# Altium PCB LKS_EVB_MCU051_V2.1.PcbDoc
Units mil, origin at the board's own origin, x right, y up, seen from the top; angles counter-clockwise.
Board outline 2625 x 1560 mil, 2 copper layers (Top Layer, Bottom Layer); 44 components, 64 nets, 193 pads, 54 vias.
Unrouted connection lines stored in the file: 24.
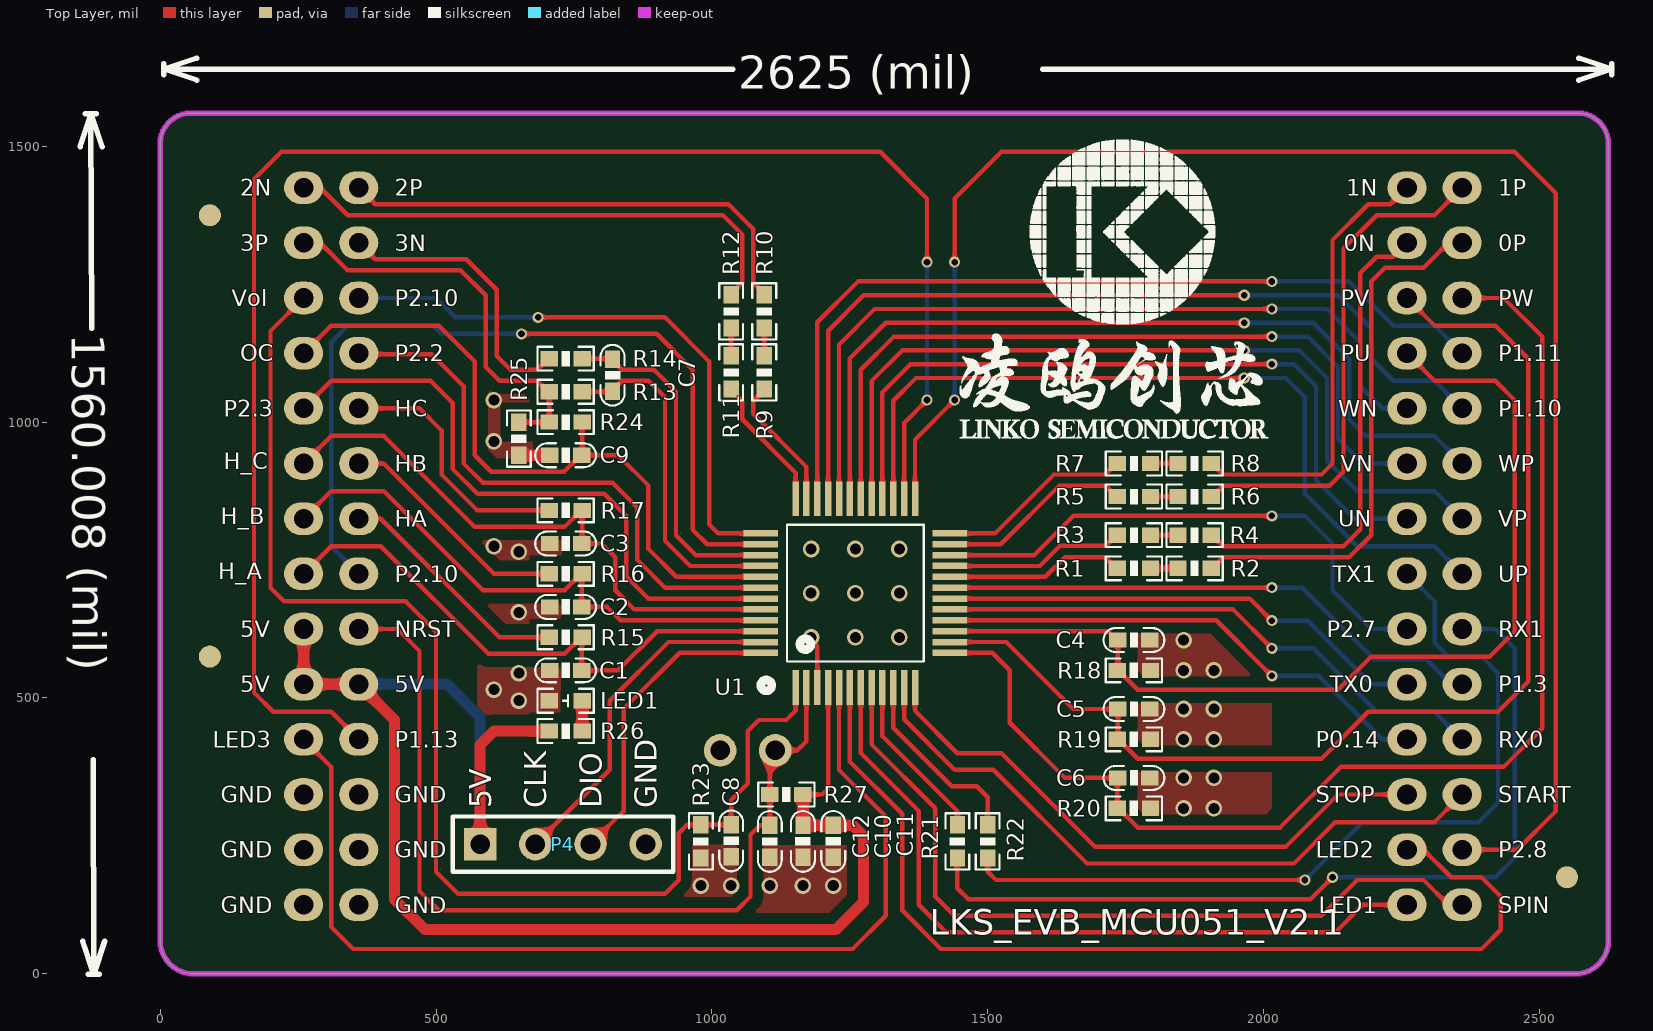
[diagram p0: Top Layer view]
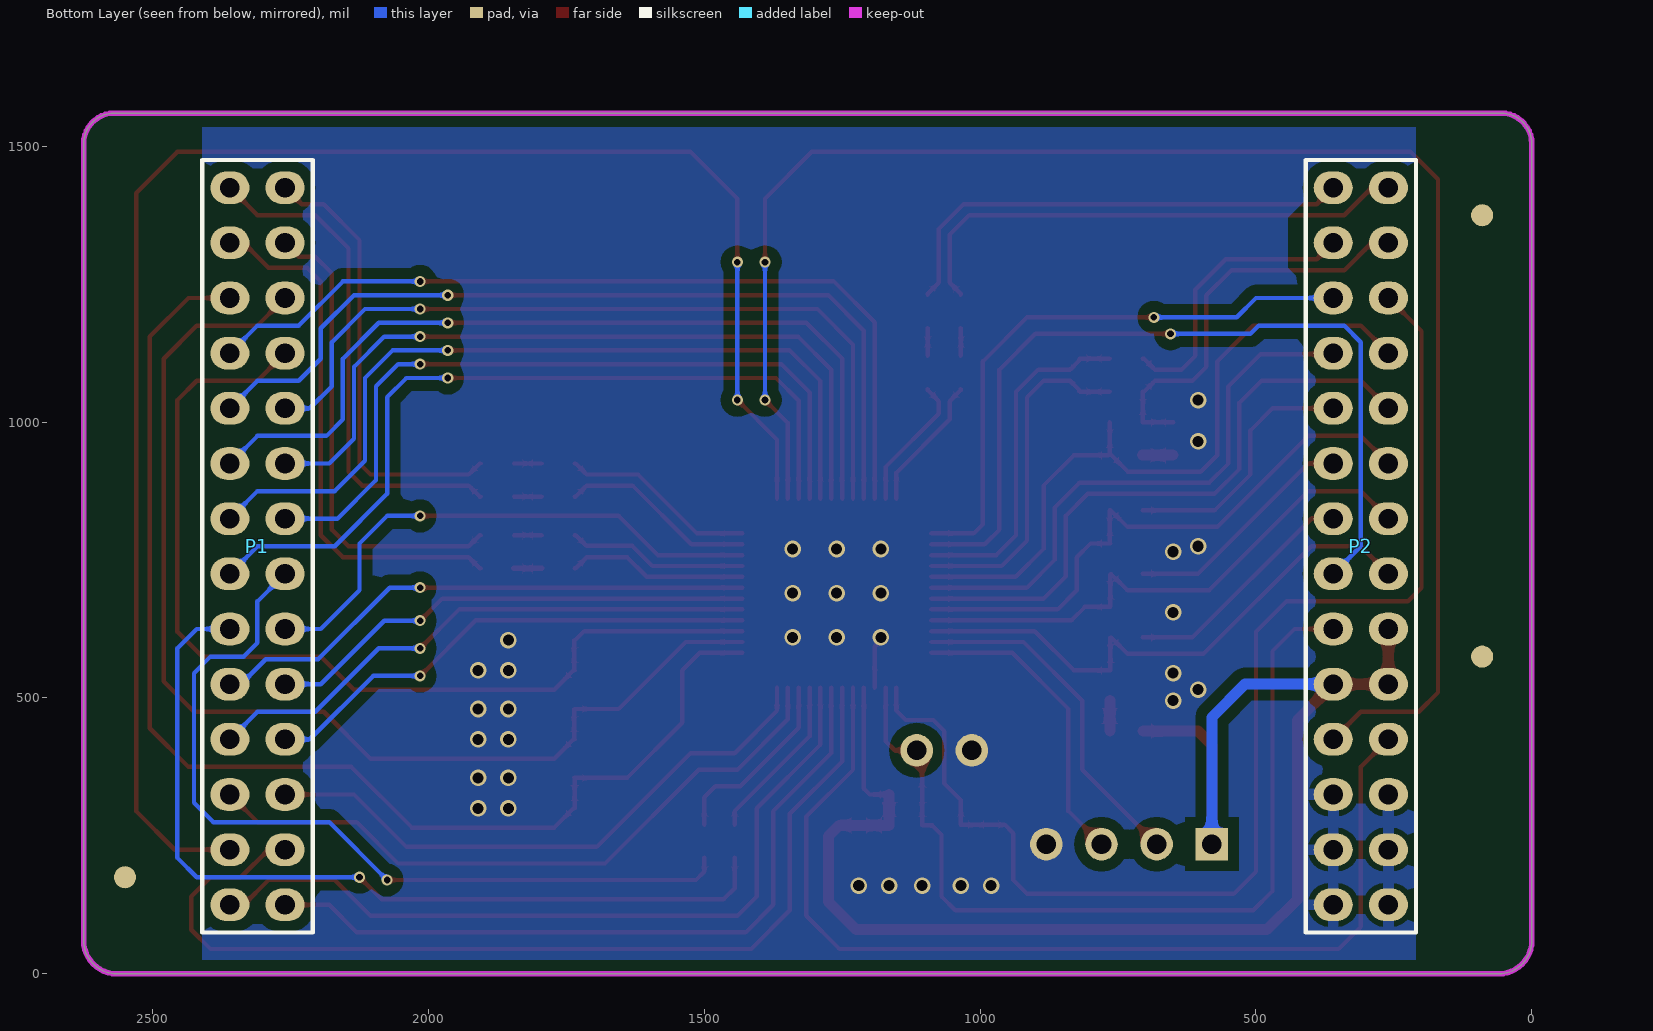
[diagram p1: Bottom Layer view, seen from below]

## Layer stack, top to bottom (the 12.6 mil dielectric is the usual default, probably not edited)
Top Solder: solder mask 0.4, Solder Resist, Dk 3.5
Top Layer: signal copper 1.4
Dielectric1: dielectric 12.6, FR-4, Dk 4.8
Bottom Layer: signal copper 1.4
Bottom Solder: solder mask 0.4, Solder Resist, Dk 3.5

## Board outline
0,60 ccw(c60,60) 60,0 2565,0 ccw(c2565,60) 2625,60 2625,1505 ccw(c2570,1505) 2570,1560 55,1560 ccw(c55,1505) 0,1505

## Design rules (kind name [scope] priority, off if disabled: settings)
Clearance Clearance_2 [InPolygon] p1: gap=20 ignorepadtopadclearanceinfootprint=FALSE except(0: Arc-Hole Track-Hole SMDPad-Hole THPad-Hole Via-Hole Fill-Hole Poly-Hole Region-Hole Text-Hole)
Clearance Clearance_1 [All] p2: gap=7.87 ignorepadtopadclearanceinfootprint=FALSE except(0: Arc-Hole Track-Hole SMDPad-Hole THPad-Hole Via-Hole Fill-Hole Poly-Hole Region-Hole Text-Hole)
ComponentClearance [All] p1: gap=0 collisioncheckmode=3 verticalgap=0 showdistances=FALSE
FabricationTestpoint [(IsPad And (OnTopLayer Or OnBottomLayer))] p1: side=3 testpointundercomponent=TRUE minsize=40 maxsize=100 preferedsize=60 minholesize=0 maxholesize=40 preferedholesize=32 testpointgrid=1 allowsidetop=TRUE allowsidebottom=TRUE usegrid=TRUE gridtolerance=0.01
PolygonConnect PolygonConnect_1 [HasFootprint('HDR 2X14 顶层') vs InNet('GND')] p1: connectstyle=Relief reliefconductorwidth=20 reliefentries=4 polygonreliefangle="90 Angle" airgapwidth=10
PolygonConnect [All] p2: connectstyle=Direct reliefconductorwidth=20 reliefentries=4 polygonreliefangle="90 Angle" airgapwidth=10
RoutingVias [All] p1: holewidth=11.81 width=23.62 viastyle="Through Hole" minholewidth=0 minwidth=11.81 maxholewidth=23.62 maxwidth=78.74
SilkToSolderMaskClearance SilkscreenOverComponentPads [IsPad] p1: minsilkscreentomaskgap=10 clearancetoexposedcopper=TRUE
SolderMaskExpansion [All] p1: expansion=4 istentingtop=FALSE
Width [All] p1: maxlimit=100 minlimit=1 preferedwidth=10
27 further rules are at their usual default settings.

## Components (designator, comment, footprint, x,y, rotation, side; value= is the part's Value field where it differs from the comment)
C1 "10nF/16V" 0603C 735,550 r180 top
C2 "10nF/16V" 0603C 735,665 r180 top
C3 "10nF/16V" 0603C 735,780 r180 top
C4 "1nF/16V" 0603C 1765,605 r0 top
C5 "1nF/16V" 0603C 1765,480 r0 top
C6 "1nF/16V" 0603C 1765,355 r0 top
C7 "1nF/10V" 0603C 820,1085 r90 top
C8 "100nF/50V" 0603C 1035,240.95 r90 top
C9 "1nF/50V" 0603C 735,940 r0 top
C10 "10uF/10V" 0603C 1165,240 r90 top
C11 "100nF/50V" 0603C 1220,240 r90 top
C12 "100nF/50V" 0603C 1105,240 r270 top
LED1 "LED" "LED 0603R" 735,495 r180 top
P1 "Header 14X2A" "HDR 2X14 顶层" 2310,775 r180 bottom locked
P2 "Header 14X2A" "HDR 2X14 顶层" 310,775 r180 bottom locked
P4 "Header 4" HDR1X4 580,235 r0 top
R1 "20K1%" 0603R 1765,735 r180 top value=K
R2 "20K1%" 0603R 1875,735 r180 top value=K
R3 "20K1%" 0603R 1765,795 r180 top value=K
R4 "20K1%" 0603R 1875,795 r180 top value=K
R5 "20K1%" 0603R 1765,865 r180 top value=K
R6 "20K1%" 0603R 1875,865 r180 top value=K
R7 "20K1%" 0603R 1765,925 r180 top value=K
R8 "20K1%" 0603R 1875,925 r180 top value=K
R9 "20K1%" 0603R 1095,1090 r270 top value=K
R10 "20K1%" 0603R 1095,1200.65 r270 top value=K
R11 "20K1%" 0603R 1035,1090 r270 top value=K
R12 "20K1%" 0603R 1035,1200.65 r270 top value=K
R13 "1K1%" 0603R 735,1055 r0 top value=K
R14 "1K1%" 0603R 735,1115 r0 top value=K
R15 "2K" 0603R 735,610 r0 top value=K
R16 "2K" 0603R 735,725 r0 top value=K
R17 "2K" 0603R 735,840 r0 top value=K
R18 "1K" 0603R 1765,550 r0 top value=K
R19 "1K" 0603R 1765,425 r0 top value=K
R20 "1K" 0603R 1765,300 r0 top value=K
R21 "10R" 0603R 1445,240 r90 top value=K
R22 "10R" 0603R 1500,240 r90 top value=K
R23 "1K1%" 0603R 980,240 r90 top value=K
R24 "1K1%" 0603R 735,1000 r180 top value=K
R25 "10R" 0603R 650,970 r270 top value=K
R26 "330R" 0603R 735,440 r0 top value=330
R27 "20K" 0603R 1135,325 r0 top value=K
U1 "LKS32MC051C6T8" TQFP48 1260,690 r0 top locked

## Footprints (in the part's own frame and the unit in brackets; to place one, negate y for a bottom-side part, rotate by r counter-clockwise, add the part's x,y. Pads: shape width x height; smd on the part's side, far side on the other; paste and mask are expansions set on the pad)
0603C [mm] "电容"
  rect 0.8x0.7 smd: 1(-0.737,0) 2(0.738,0)
  silkscreen extent -1.4,-0.55 1.4,0.55, body extent -0.8,-0.41 0.8,0.41, height 0.81
0603R [mm] "电阻"
  rect 0.8x0.7 smd: 1(-0.762,0) 2(0.762,0)
  silkscreen extent -1.3,-0.55 1.3,0.55, body extent -0.8,-0.4 0.8,0.4, height 0.45
HDR1X4 [mm] "Connector; Header; 4 Position"
  rect 1.5x1.5 hole 0.9: 1(0,0)
  round 1.5 hole 0.9: 2(2.54,0) 3(5.08,0) 4(7.62,0)
  silkscreen extent -1.27,-1.27 8.89,1.27
"HDR 2X14 顶层" [mm] "双排针 2.54mm 顶层"
  oval 1.8x1.5 hole 0.9: 1(1.27,16.51) 2(1.27,13.97) 3(1.27,11.43) 4(1.27,8.89) 5(1.27,6.35) 6(1.27,3.81) 7(1.27,1.27) 8(1.27,-1.27) 9(1.27,-3.81) 10(1.27,-6.35) 11(1.27,-8.89) 12(1.27,-11.43) 13(1.27,-13.97) 14(1.27,-16.51) 15(-1.27,16.51) 16(-1.27,13.97) 17(-1.27,11.43) 18(-1.27,8.89) 19(-1.27,6.35) 20(-1.27,3.81) 21(-1.27,1.27) 22(-1.27,-1.27) 23(-1.27,-3.81) 24(-1.27,-6.35) 25(-1.27,-8.89) 26(-1.27,-11.43) 27(-1.27,-13.97) 28(-1.27,-16.51)
  silkscreen extent -2.54,-17.78 2.54,17.78, body extent -2.54,-17.78 2.54,17.78, height 8.5
"LED 0603R" [mm] "LED"
  rect 0.8x0.7 smd: 1(-0.762,0) 2(0.762,0)
  silkscreen extent -1.3,-0.55 1.3,0.55, body extent -0.8,-0.4 0.8,0.4, height 0.47
TQFP48 [mm] "LINKO-081/083/088/051"
  rect 0.3x1.6 smd: 1(-2.75,-4.35) 2(-2.25,-4.35) 3(-1.75,-4.35) 4(-1.25,-4.35) 5(-0.75,-4.35) 6(-0.25,-4.35) 7(0.25,-4.35) 8(0.75,-4.35) 9(1.25,-4.35) 10(1.75,-4.35) 11(2.25,-4.35) 12(2.75,-4.35) 25(2.75,4.35) 26(2.25,4.35) 27(1.75,4.35) 28(1.25,4.35) 29(0.75,4.35) 30(0.25,4.35) 31(-0.25,4.35) 32(-0.75,4.35) 33(-1.25,4.35) 34(-1.75,4.35) 35(-2.25,4.35) 36(-2.75,4.35)
  rect 1.6x0.3 smd: 13(4.35,-2.75) 14(4.35,-2.25) 15(4.35,-1.75) 16(4.35,-1.25) 17(4.35,-0.75) 18(4.35,-0.25) 19(4.35,0.25) 20(4.35,0.75) 21(4.35,1.25) 22(4.35,1.75) 23(4.35,2.25) 24(4.35,2.75) 37(-4.35,2.75) 38(-4.35,2.25) 39(-4.35,1.75) 40(-4.35,1.25) 41(-4.35,0.75) 42(-4.35,0.25) 43(-4.35,-0.25) 44(-4.35,-0.75) 45(-4.35,-1.25) 46(-4.35,-1.75) 47(-4.35,-2.25) 48(-4.35,-2.75)
  silkscreen extent -4.35,-4.5 3.15,3.15, body extent -4.5,-4.5 4.5,4.5, height 1.05

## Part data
C1 C2 C3 C4 C5 C6: library part CAP, "Capacitor"
C7 C8 C9 C10 C11 C12: library part C, "Capacitor"
LED1: "LED_Light"
P1 P2: "Header, 14-Pin, Dual row"
P4: "Header, 4-Pin"
R1 R2 R3 R4 R5 R6 R7 R8 R9 R10 R11 R12 R13 R14 R15 R16 R17 R18 R19 R20 R21 R22 R23 R24 R25 R26 R27: library part Res, "Resistor"
U1: "芯片"

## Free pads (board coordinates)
  round 59.06 hole 35.43: 1(1015,405) 1(1115,405)
  round 40 all layers, no hole: 1(2550,175) 2(90,1375) 3(90,575)

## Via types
v1: diameter 30, hole 20, Top Layer to Bottom Layer, 33 vias
v2: diameter 20, hole 12, Top Layer to Bottom Layer, 21 vias

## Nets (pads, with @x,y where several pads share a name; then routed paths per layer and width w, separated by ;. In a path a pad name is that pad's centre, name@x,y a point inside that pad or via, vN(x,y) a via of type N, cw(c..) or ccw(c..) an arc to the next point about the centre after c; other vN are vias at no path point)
+5V: C10.2 C11.2 P2.9 P2.10 P2.24 P4.1 R26.1 R27.2 U1.4 | length 2827.7
  Top Layer w8: R27.2 1200,325 1210.79,335.79 U1.4
  Top Layer w20: P2.9 P2.10 P2.24 425,460 425,135 480,80 1225,80 1275,130 1275,250 1255.94,269.06 C11.2 C10.2 R27.2 ; P4.1 580,415 605,440 R26.1
  Bottom Layer w20: P2.24 520,525 580,465 P4.1
GND: C1.2 C2.2 C3.2 C4.2 C5.2 C6.2 C8.1 C9.1 C10.1 C11.1 C12.2 LED1.2 P2.12 P2.13 P2.14 P2.16 P2.26 P2.27 P2.28 P4.4 pad.1@1015,405 R14.1 R18.2 R19.2 R20.2 R23.1 R25.2 U1.3 | length 670.7
  Top Layer w8: P2.16 390,1295 555,1295 610,1240 610,1120 635,1095 683.03,1095 703.03,1115 R14.1 ; v1(1180,610) 1180,604.05 1191.1,592.94 U1.3
  Top Layer w20: R25.2 C9.1
  other v1: 980,160 1035,160 1105,160 1165,160 1220,160 1855,300 1910,300 1855,355 1910,355 1855,425 1910,425 1855,480 1910,480 650,495 605,515 650,545 1855,550 1910,550 1855,605 1260,610 1340,610 650,655 1180,690 1260,690 1340,690 650,765 1180,770 1260,770 1340,770 605,775 605,965 605,1040
HALL_U: C1.1 P2.8 R15.2 U1.46 | length 1030.7
  Top Layer w8: P2.8 310,775 400,775 595,580 733.03,580 762.03,609 764,609 C1.1 830,550 901.1,621.1 U1.46
HALL_V: C2.1 P2.7 R16.2 U1.45 | length 1005.1
  Top Layer w8: P2.7 310,875 405,875 585,695 733.03,695 762.03,724 764,724 C2.1 810,665 834.21,640.79 U1.45
HALL_W: C3.1 P2.6 R17.2 U1.44 | length 1076.3
  Top Layer w8: P2.6 310,975 405,975 570,810 733.03,810 763.03,840 R17.2 765,781 C3.1 800,780 825,755 825,695 859.53,660.47 U1.44
HU: P2.21 R15.1 | length 434.1
  Top Layer w8: P2.21 400,825 615,610 R15.1
HV: P2.20 R16.1 | length 427.8
  Top Layer w8: P2.20 405,925 605,725 R16.1
HW: P2.19 R17.1 | length 468.5
  Top Layer w8: P2.19 470,1025 510,985 510,905 575,840 R17.1
LED1: P1.14 U1.7 | length 1363.7
  Top Layer w8: U1.7 1269.84,400.16 1375,295 1375,125 1425,75 2130,75 2180,125 P1.14
LED2: P1.13 U1.6 | length 1836.7
  Top Layer w8: U1.6 1250.16,384.84 1345,290 1345,115 1415,45 2395,45 2430,80 2430,140 2395,175 2340,175 2290,225 P1.13
LED3: P2.11 U1.5 | length 1855.9
  Top Layer w8: P2.11 310,375 310,85 350,45 1255,45 1315,105 1315,285 1230.47,369.53 U1.5
NetLED1_1: LED1.1 R26.2 | length 55
  Top Layer w20: R26.2 LED1.1
NetR1_1: R1.1 R2.2 | length 50
  Top Layer w10: R1.1 R2.2
NetR3_1: R3.1 R4.2 | length 50
  Top Layer w8: R3.1 R4.2
NetR5_1: R5.1 R6.2 | length 50
  Top Layer w8: R5.1 R6.2
NetR7_1: R7.1 R8.2 | length 50
  Top Layer w8: R7.1 R8.2
NetR9_1: R9.1 R10.2 | length 50.7
  Top Layer w8: R9.1 R10.2
NetR11_1: R11.1 R12.2 | length 50.7
  Top Layer w8: R11.1 R12.2
NetR21_2: R21.2 U1.9 | length 305
  Top Layer w8: U1.9 1309.21,430.79 1445,295 R21.2
NetR22_2: R22.2 U1.10 | length 346
  Top Layer w8: U1.10 1328.9,446.1 1435,340 1480,340 1500,320 R22.2
NRST: C12.1 P2.23 pad.1@1115,405 R27.1 U1.2 | length 1659.3
  Top Layer w8: P2.23 430,625 470,585 470,150 505,115 1045,115 1070,140 1070,252.24 1086.76,269 C12.1 R27.1 1105,395 pad.1@1115,405 ; pad.1@1096.97,405 pad.1@1115,405 ; U1.2 1171.42,421.42 1155,405 pad.1@1115,405
OC: C9.2 P2.4 R24.1 U1.41 | length 1289.4
  Top Layer w8: P2.4 310,1175 505,1175 570,1110 570,940 600,910 732.09,910 C9.2@765,942.91 ; R24.1 C9.2@765,942.91 ; U1.41 935.47,719.53 885,770 885,885 830,940 767.91,940 C9.2@765,942.91
OPA0_IN: R11.2 U1.36 | length 247.1
  Top Layer w8: R11.2 1035,1058.03 1055,1038.03 1055,1005 1151.73,908.27 U1.36
OPA0_IP: R9.2 U1.35 | length 247
  Top Layer w8: R9.2 1095,1058.03 1075,1038.03 1075,1015 1171.42,918.58 U1.35
OPA1_IN: C7.2 R14.2 U1.39 | length 624.7
  Top Layer w8: R14.2 819.05,1115 C7.2 820,1112.09 837.09,1095 895,1095 935,1055 935,795 971.1,758.9 U1.39
OPA1_IP: C7.1 R13.2 U1.40 | length 624.6
  Top Layer w8: R13.2 819,1055 C7.1 820,1057.97 837.03,1075 885,1075 915,1045 915,785 960.79,739.21 U1.40
OPA2_IN: R3.2 U1.21 | length 326.8
  Top Layer w8: U1.21 1594.21,739.21 1630.87,775.87 1713.91,775.87 1733.03,795 R3.2
OPA2_IP: R1.2 U1.20 | length 326.7
  Top Layer w8: U1.20 1604.53,719.53 1640,755 1713.03,755 1733.03,735 R1.2
OPA3_IN: R7.2 U1.24 | length 356.2
  Top Layer w8: U1.24 1513.27,798.27 1620,905 1713.03,905 1733.03,925 R7.2
OPA3_IP: R5.2 U1.23 | length 356.1
  Top Layer w8: U1.23 1523.58,778.58 1630,885 1713.03,885 1733.03,865 R5.2
P0.14: P1.11 U1.16 | length 918.1
  Top Layer w8: U1.16 1914.21,640.79 v2(2015,540)
  Bottom Layer w8: v2(2015,540) 2100,540 2215,425 P1.11
P1.3: P1.24 U1.19 | length 1001.2
  Top Layer w8: U1.19 v2(2015.16,699.84)
  Bottom Layer w8: v2(2015.16,699.84) 2070.16,699.84 2200,570 2295,570 2340,525 P1.24
P1.10: P1.19 U1.33 | length 1597.5
  Top Layer w8: U1.33 1210.79,1165.79 1275,1230 v2(1965,1230)
  Bottom Layer w8: v2(1965,1230) 2135,1230 2195,1170 2195,1115 2235,1075 2310,1075 P1.19
P1.11: P1.18 U1.34 | length 1573.2
  Top Layer w8: U1.34 1191.1,1181.1 1265,1255 v2(2015,1255)
  Bottom Layer w8: v2(2015,1255) 2155,1255 2235,1175 2310,1175 P1.18
P1.13: P2.25 U1.26 | length 2992
  Top Layer w8: P2.25 310,475 205,475 170,510 170,1440 220,1490 1305,1490 1390,1405 v2(1390,1290) ; U1.26 1348.58,998.58 v2(1390,1040)
  Bottom Layer w8: v2(1390,1040) v2(1390,1290)
P2.2: P2.18 U1.42 | length 1042.5
  Top Layer w8: P2.18 361.87,1123.13 491.87,1123.13 550,1065 550,925 585,890 820,890 865,845 865,750 915.16,699.84 U1.42
P2.3: P2.5 U1.43 | length 1147.7
  Top Layer w8: P2.5 310,1075 490,1075 530,1035 530,915 575,870 805,870 845,830 845,720 884.84,680.16 U1.43
P2.7: P1.9 U1.22 | length 992.9
  Top Layer w8: U1.22 1583.9,758.9 1655,830 v2(2015,830)
  Bottom Layer w8: v2(2015,830) 2075,830 2125,780 2125,695 2195,625 P1.9
P2.8: P1.27 U1.25 | length 3048.7
  Top Layer w8: U1.25 1368.27,968.27 v2(1440,1040) ; v2(1440,1290) 1440,1405 1525,1490 2455,1490 2530,1415 2530,295 2460,225 P1.27
  Bottom Layer w8: v2(1440,1040) v2(1440,1290)
P2.9: P2.17 U1.37 | length 1078.3
  Top Layer w8: v2(685,1190) 915,1190 995,1110 995,815 1011.73,798.27 U1.37
  Bottom Layer w8: P2.17 500,1225 535,1190 v2(685,1190)
P2.10: P2.22 U1.38 | length 1566
  Top Layer w8: v2(655,1160) 900,1160 965,1095 965,805 991.42,778.58 U1.38
  Bottom Layer w8: P2.22 310,775 310,1145 340,1175 495,1175 510,1160 v2(655,1160)
PGND: P1.1 P1.2 P2.1 P2.2 R4.1 R8.1 R12.1 R13.1 R24.2 R25.1 | length 3370.2
  Top Layer w8: P2.2 290,1325 340,1275 545,1275 590,1230 590,1100 615,1075 683.03,1075 703.03,1055 R13.1 R24.2 R25.1 ; P2.1 290,1425 340,1375 1020,1375 1055,1340 1055,1252.62 1035,1232.62 R12.1 ; R4.1 1906.97,795 1926.97,775 2145,775 2175,805 2175,1270 2205,1300 2235,1300 P1.2 ; R8.1 1906.97,925 1926.97,905 2105,905 2125,925 2125,1330 2190,1395 2230,1395 P1.1
PU: C4.1 P1.4 R18.1 U1.15 | length 1795
  Top Layer w8: U1.15 1717.93,621.1 1734.03,605 C4.1 1736,551 R18.1 1736.97,550 1771.97,515 2135,515 2195,575 2410,575 2455,620 2455,1040 2420,1075 2310,1075 P1.4
PV: C5.1 P1.3 R19.1 U1.14 | length 2078.5
  Top Layer w8: U1.14 1533.58,601.42 1655,480 C5.1 1736,426 R19.1 1736.97,425 1771.97,390 2105,390 2190,475 2425,475 2480,530 2480,1115 2420,1175 2310,1175 P1.3
PW: C6.1 P1.17 R20.1 U1.13 | length 2252.8
  Top Layer w8: U1.13 1508.27,581.73 1540,550 1540,455 1640,355 C6.1 1735,354 R20.1 1736.97,300 1771.97,265 2030,265 2140,375 2435,375 2505,445 2505,1155 2435,1225 P1.17
RXD0: P1.25 U1.17 | length 1026.3
  Top Layer w8: U1.17 1944.53,660.47 v2(2015,590)
  Bottom Layer w8: v2(2015,590) 2090,590 2205,475 2310,475 P1.25
RXD1: P1.23 R21.1 | length 1593.8
  Top Layer w8: R21.1 1445,155 1465,135 2085,135 v2(2125,175)
  Bottom Layer w8: v2(2125,175) 2420,175 2455,210 2455,590 2420,625 P1.23
SPIN: P1.28 U1.8 | length 1441.6
  Top Layer w8: U1.8 1289.53,415.47 1405,300 1405,140 1440,105 2105,105 2170,170 2290,170 2335,125 P1.28
START1: P1.26 U1.11 | length 1228.8
  Top Layer w8: U1.11 1348.58,461.42 1440,370 1510,370 1680,200 2055,200 2130,275 2310,275 P1.26
STOP1: P1.12 U1.12 | length 1075.3
  Top Layer w8: U1.12 1368.27,476.73 1445,400 1525,400 1695,230 2040,230 2135,325 P1.12
SWCLK: P4.2 U1.47 | length 633.7
  Top Layer w8: P4.2 815,370 815,495 921.42,601.42 U1.47
SWDIO: P4.3 U1.48 | length 560.7
  Top Layer w8: P4.3 840,295 840,480 941.73,581.73 U1.48
TXD0: P1.10 U1.18 | length 893
  Top Layer w8: U1.18 1974.84,680.16 v2(2015,640)
  Bottom Layer w8: v2(2015,640) 2080,640 2195,525 P1.10
TXD1: P1.8 R22.1 | length 1532.7
  Top Layer w8: R22.1 1500,185 1515,170 v2(2075,170)
  Bottom Layer w8: v2(2075,170) 2180,275 2390,275 2425,310 2425,545 2395,575 2335,575 2310,600 2310,675 P1.8
UN: P1.7 U1.28 | length 1380.3
  Top Layer w8: U1.28 1309.21,1054.21 1360,1105 v2(2015,1105)
  Bottom Layer w8: v2(2015,1105) 2055,1105 2095,1065 2095,895 2165,825 P1.7
UP: P1.22 U1.27 | length 1475.3
  Top Layer w8: U1.27 1328.9,1038.9 1370,1080 v2(1965,1080)
  Bottom Layer w8: v2(1965,1080) 2040,1080 2075,1045 2075,870 2170,775 2310,775 P1.22
UP-: P2.15 R10.1 | length 873.7
  Top Layer w8: P2.15 390,1395 1030,1395 1075,1350 1075,1252.62 1095,1232.62 R10.1
VN: P1.6 U1.30 | length 1420.1
  Top Layer w8: U1.30 1269.84,1094.84 1330,1155 v2(2015,1155)
  Bottom Layer w8: v2(2015,1155) 2080,1155 2135,1100 2135,970 2180,925 P1.6
VOL_ADC: C8.2 P2.3 R23.2 U1.1 | length 2297.5
  Top Layer w8: P2.3 200,1165 200,700 225,675 445,675 500,620 500,185 540,145 915,145 940,170 940,255 955,270 R23.2 C8.2 1035,315 1065,345 1065,440 1085,460 1135,460 1151.73,476.73 U1.1
VP: P1.21 U1.29 | length 1520.9
  Top Layer w8: U1.29 1289.53,1074.53 1345,1130 v2(1965,1130)
  Bottom Layer w8: v2(1965,1130) 2065,1130 2115,1080 2115,930 2170,875 2310,875 P1.21
VP-: P1.15 R6.1 | length 924.2
  Top Layer w8: R6.1 1906.97,865 1926.97,885 2120,885 2145,910 2145,1315 2205,1375 2310,1375 P1.15
WN: P1.5 U1.32 | length 1456.9
  Top Layer w8: U1.32 1230.47,1140.47 1295,1205 v2(2015,1205)
  Bottom Layer w8: v2(2015,1205) 2115,1205 2175,1145 2175,1065 2215,1025 P1.5
WP: P1.20 U1.31 | length 1560.7
  Top Layer w8: U1.31 1250.16,1115.16 1315,1180 v2(1965,1180)
  Bottom Layer w8: v2(1965,1180) 2090,1180 2155,1115 2155,1005 2185,975 2310,975 P1.20
WP-: P1.16 R2.1 | length 968.8
  Top Layer w7.87: R2.1 R2.1@1906.97,735
  Top Layer w8: R2.1@1906.97,735 1926.97,755 2155,755 2195,795 2195,1255 2220,1280 2290,1280 2326.14,1316.14 2351.14,1316.14 P1.16

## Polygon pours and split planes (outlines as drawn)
GND on Top Layer "10" (solid, remove dead copper, pour order 27): 725,470 590,470 575,485 575,1020 570,1025 570,1060 585,1075 635,1075 675,1035 675,827.35 692.35,810 720,810 727.52,802.48 727.52,766.02
GND on Top Layer "NONET_L-01_P-001" (solid, remove dead copper, pour order 25): 1765,640 2015,640 2015,300 1980,265 1770,265 1765,270
GND on Top Layer "10" (solid, remove dead copper, pour order 26): 940,240 1255,240 1275,220 1275,125 1230,80 940,80
GND on Bottom Layer "Top Layer-No Net 1" (solid, remove dead copper, pour order 14): 210,0 2410,0 2410,1560 210,1560

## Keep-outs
Keep-Out Layer:
  the board outline again, w10

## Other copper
Top Layer:
  pour cut-out: 805,1145 695,1145 690,1150 690,1250 565,1375 395,1375 385,1365 385,1270 595,1270 650,1215 650,1095 665,1080 805,1080
Bottom Layer:
  pour cut-out: 197.5,1400 412.5,1400 442.5,1370 442.5,1280 427.48,1264.98 197.5,1264.98

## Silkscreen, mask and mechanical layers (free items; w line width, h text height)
Top Overlay:
  drawing of 160 lines, arcs and shapes, not listed
  text "2625 (mil)" at 1048.18,1604.01 h60
  text "2N" at 145,1410 h30
  text "2P" at 425,1410 h30
  text "1N" at 2150,1410 h30
  text "1P" at 2425,1410 h30
  text "3P" at 145,1310 h30
  text "3N" at 425,1310 h30
  text "0N" at 2145,1310 h30
  text "0P" at 2425,1310 h30
  text "Vol" at 130,1210 h30
  text "P2.10" at 425,1210 h30
  text "PV" at 2140,1210 h30
  text "PW" at 2425,1210 h30
  text "1560.008 (mil)" at -160.24,1159.98 h60 r270.18
  text "OC" at 145,1110 h30
  text "P2.2" at 425,1110 h30
  text "PU" at 2140,1110 h30
  text "P1.11" at 2425,1110 h30
  text "P2.3" at 115,1010 h30
  text "HC" at 425,1010 h30
  text "WN" at 2135,1010 h30
  text "P1.10" at 2425,1010 h30
  text "H_C" at 115,915 h30
  text "HB" at 425,910 h30
  text "VN" at 2140,910 h30
  text "WP" at 2425,910 h30
  text "H_B" at 110,815 h30
  text "HA" at 425,810 h30
  text "UN" at 2135,810 h30
  text "VP" at 2425,810 h30
  text "H_A" at 105,715 h30
  text "P2.10" at 425,710 h30
  text "TX1" at 2125,710 h30
  text "UP" at 2425,710 h30
  text "5V" at 145,610 h30
  text "NRST" at 425,610 h30
  text "P2.7" at 2115,610 h30
  text "RX1" at 2425,610 h30
  text "5V" at 145,510 h30
  text "5V" at 425,510 h30
  text "TX0" at 2120,510 h30
  text "P1.3" at 2425,510 h30
  text "LED3" at 95,410 h30
  text "P1.13" at 425,410 h30
  text "P0.14" at 2095,410 h30
  text "RX0" at 2425,410 h30
  text "GND" at 110,310 h30
  text "GND" at 425,310 h30
  text "STOP" at 2095,310 h30
  text "START" at 2425,310 h30
  text "5V" at 600,300 h40 r90
  text "CLK" at 700,300 h40 r90
  text "DIO" at 800,300 h40 r90
  text "GND" at 900,300 h40 r90
  text "GND" at 110,210 h30
  text "GND" at 425,210 h30
  text "LED2" at 2095,210 h30
  text "P2.8" at 2425,210 h30
  text "GND" at 110,110 h30
  text "GND" at 425,110 h30
  text "LED1" at 2100,110 h30
  text "SPIN" at 2425,110 h30
  text "LKS_EVB_MCU051_V2.1" at 1395,55 h78.74
Top Solder:
  circle w77.95: c2550,175 r17.01
  circle w77.95: c90,1375 r17.01
  circle w77.99: c90,575 r17.01
Mechanical 1:
  the board outline again, w10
